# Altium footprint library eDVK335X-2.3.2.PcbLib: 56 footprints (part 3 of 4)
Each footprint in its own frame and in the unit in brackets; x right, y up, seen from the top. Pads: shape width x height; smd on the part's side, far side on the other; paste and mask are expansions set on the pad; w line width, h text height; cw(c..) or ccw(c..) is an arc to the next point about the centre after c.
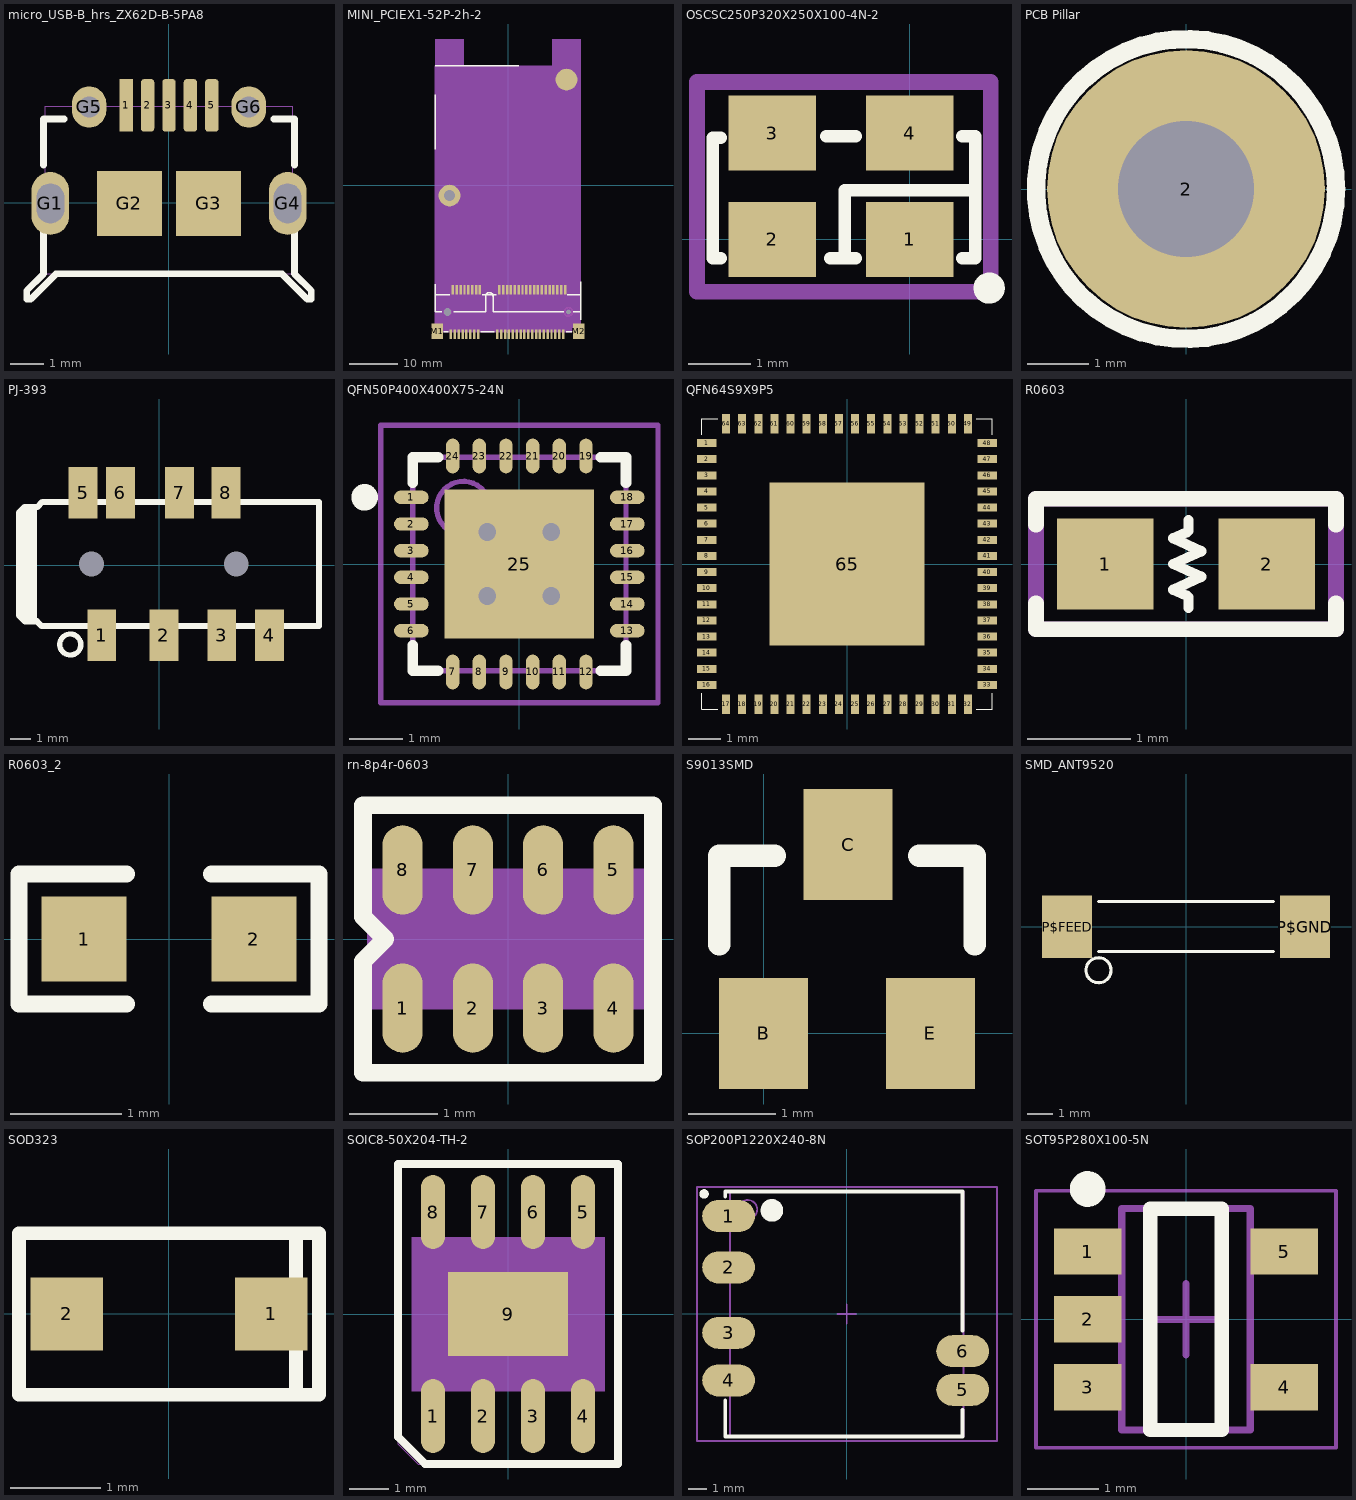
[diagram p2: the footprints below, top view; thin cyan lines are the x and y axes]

## micro_USB-B_hrs_ZX62D-B-5PA8 [mil] "MICRO_USB-B_HRS_ZX62D-B-5PA8"
pads (11):
  rect 16x63 smd: 1(-51.18,116.29)
  rrect50% 16x63 smd: 2(-25.59,116.29) 3(0,116.29) 4(25.59,116.29) 5(51.18,116.29)
  oval 45x75 / inner round 60 / far side oval 45x75 hole 33 slot 47.24 at 90 deg: G1(-141.73,-0.84) G4(141.74,-0.84)
  rect 78x78 smd: G2(-47.24,-0.84) G3(47.25,-0.84)
  oval 41.34x49.21 / inner round 60 / far side oval 41.34x49.21 hole 25.59: G5(-95.47,114.37) G6(95.47,114.37)
Top Overlay:
  lines w7.87: -150,-30.04 -150,-85.04 -170,-105.04 -170,-115.04 -165,-115.04 -135,-85.04 135,-85.04 165,-115.04 170,-115.04 170,-105.04 150,-85.04 150,-30.04 ; -150,45 -150,100 -125,100 ; 125,100 150,100 150,45
Mechanical 8:
  text "1" at -55.18,116.29 h10
  text "2" at -29.59,116.29 h10
  text "3" at -4,116.29 h10
  text "G1" at -149.73,-0.84 h10
  text "G5" at -103.47,114.37 h10
  text "G2" at -55.24,-0.84 h10
  text "4" at 21.59,116.29 h10
  text "5" at 47.18,116.29 h10
  text "G6" at 87.47,114.37 h10
  text "G3" at 39.25,-0.84 h10
Mechanical 10:
  lines w1: -135,-85.04 -165,-115.04 -170,-115.04 -170,-105.04 -168,-105.04 -148,-85.04 ; 135,-85.04 165,-115.04 170,-115.04 170,-105.04 168,-105.04 148,-85.04 ; -148,-85.04 -148,114.96 148,114.96 148,-85.04 ; -148,-85.04 148,-85.04

## MINI_PCIEX1-52P-2h-2 [mm] "MINI_PCIEX1-52P-2H-2"
pads (58):
  rect 0.508x2.007 smd: 1(-11.8,-30.775) 2(-11.4,-21.575) 3(-11,-30.775) 4(-10.6,-21.575) 5(-10.2,-30.775) 6(-9.8,-21.575) 7(-9.4,-30.775) 8(-9,-21.575) 9(-8.6,-30.775) 10(-8.2,-21.575) 11(-7.8,-30.775) 12(-7.4,-21.575) 13(-7,-30.775) 14(-6.6,-21.575) 15(-6.2,-30.775) 16(-5.8,-21.575) 17(-2.2,-30.775) 18(-1.8,-21.575) 19(-1.4,-30.775) 20(-1,-21.575) 21(-0.6,-30.775) 22(-0.2,-21.575) 23(0.2,-30.775) 24(0.6,-21.575) 25(1,-30.775) 26(1.4,-21.575) 27(1.8,-30.775) 28(2.2,-21.575) 29(2.6,-30.775) 30(3,-21.575) 31(3.4,-30.775) 32(3.8,-21.575) 33(4.2,-30.775) 34(4.6,-21.575) 35(5,-30.775) 36(5.4,-21.575) 37(5.8,-30.775) 38(6.2,-21.575) 39(6.6,-30.775) 40(7,-21.575) 41(7.4,-30.775) 42(7.8,-21.575) 43(8.2,-30.775) 44(8.6,-21.575) 45(9,-30.775) 46(9.4,-21.575) 47(9.8,-30.775) 48(10.2,-21.575) 49(10.6,-30.775) 50(11,-21.575) 51(11.4,-30.775) 52(11.8,-21.575)
  round 0 hole 1.6 unplated: G1(-12.5,-26.175)
  round 0 hole 1.092 unplated: G2(12.5,-26.175)
  rect 2.311x3.2 smd: M1(-14.65,-30.175) M2(14.65,-30.175)
  round 4.5 / inner round 1.524 / far side round 3 all layers, no hole: mPCIe_PIL(12.1,21.875)
  round 4.5 / inner round 1.524 / far side round 3 hole 2.3: ""(-12.095,-2.105)
Top Overlay:
  lines w0.3: -15,-22.675 -12,-22.675 ; -15,-20.425 -15,-26.175 -13.7,-26.175 ; -15,7.5 -15,18.725 ; -15,24.765 2.265,24.765 ; -13.3,-30.275 -12.4,-30.275 ; -11.2,-26.175 -4.6,-26.175 -4.6,-22.925 cw(c-3.85,-22.925) -3.1,-22.925 -3.1,-26.175 11.5,-26.175 ; -5.6,-30.275 -2.8,-30.275 ; -5.3,-22.675 -2.4,-22.675 ; 12,-30.275 13.3,-30.275 ; 12.3,-22.675 15,-22.675 ; 13.5,-26.175 15,-26.175 ; 15,-27.775 15,-19.975
Mechanical 8:
  text "52" at 11.597,-21.575 h0.25
  text "50" at 10.797,-21.575 h0.25
  text "48" at 9.997,-21.575 h0.25
  text "G2" at 12.297,-26.175 h0.25
  text "42" at 7.597,-21.575 h0.25
  text "40" at 6.797,-21.575 h0.25
  text "46" at 9.197,-21.575 h0.25
  text "44" at 8.397,-21.575 h0.25
  text "32" at 3.597,-21.575 h0.25
  text "34" at 4.397,-21.575 h0.25
  text "30" at 2.797,-21.575 h0.25
  text "38" at 5.997,-21.575 h0.25
  text "36" at 5.197,-21.575 h0.25
  text "24" at 0.397,-21.575 h0.25
  text "22" at -0.403,-21.575 h0.25
  text "28" at 1.997,-21.575 h0.25
  text "26" at 1.197,-21.575 h0.25
  text "M2" at 14.447,-30.175 h0.25
  text "51" at 11.197,-30.775 h0.25
  text "49" at 10.397,-30.775 h0.25
  text "47" at 9.597,-30.775 h0.25
  text "45" at 8.797,-30.775 h0.25
  text "43" at 7.997,-30.775 h0.25
  text "41" at 7.197,-30.775 h0.25
  text "33" at 3.997,-30.775 h0.25
  text "35" at 4.797,-30.775 h0.25
  text "31" at 3.197,-30.775 h0.25
  text "39" at 6.397,-30.775 h0.25
  text "37" at 5.597,-30.775 h0.25
  text "25" at 0.797,-30.775 h0.25
  text "23" at -0.003,-30.775 h0.25
  text "29" at 2.397,-30.775 h0.25
  text "27" at 1.597,-30.775 h0.25
  text "20" at -1.203,-21.575 h0.25
  text "18" at -2.003,-21.575 h0.25
  text "16" at -6.003,-21.575 h0.25
  text "8" at -9.102,-21.575 h0.25
  text "10" at -8.403,-21.575 h0.25
  text "6" at -9.902,-21.575 h0.25
  text "14" at -6.803,-21.575 h0.25
  text "12" at -7.603,-21.575 h0.25
  text "4" at -10.702,-21.575 h0.25
  text "2" at -11.502,-21.575 h0.25
  text "G1" at -12.703,-26.175 h0.25
  text "19" at -1.603,-30.775 h0.25
  text "21" at -0.803,-30.775 h0.25
  text "17" at -2.403,-30.775 h0.25
  text "11" at -8.003,-30.775 h0.25
  text "15" at -6.403,-30.775 h0.25
  text "13" at -7.203,-30.775 h0.25
  text "7" at -9.502,-30.775 h0.25
  text "9" at -8.702,-30.775 h0.25
  text "3" at -11.102,-30.775 h0.25
  text "5" at -10.302,-30.775 h0.25
  text "M1" at -14.853,-30.175 h0.25
  text "1" at -11.902,-30.775 h0.25
Mechanical 9:
  region: -2.4,-20.775 -2.4,-22.675 12.5,-22.675 12.5,-20.775
  region: 15,30.275 15,18.975 9.2,18.975 9.2,20.825 -9.2,20.825 -9.2,18.975 -15,18.975 -15,30.275 -9.2,30.275 -9.2,24.775 9.2,24.775 9.2,30.275
  region: -5.2,-20.775 -5.2,-22.675 -12,-22.675 -12,-20.775
  region: 15,-22.675 15,18.975 9.2,18.975 9.2,20.825 -9.2,20.825 -9.2,18.975 -15,18.975 -15,-22.675 -12,-22.675 -12,-20.775 -5.2,-20.775 -5.2,-22.675 -2.4,-22.675 -2.4,-20.775 12.5,-20.775 12.5,-22.675
  region: 15,-22.675 15,-30.275 -15,-30.275 -15,-22.675
Mechanical 10:
  lines w0.025: -15,-30.275 15,-30.275 15,-22.675 -15,-22.675 -15,-30.275 ; -15,-26.175 -4.6,-26.175 -4.6,-22.925 cw(c-3.85,-22.925) -3.1,-22.925 -3.1,-26.175 15,-26.175 15,24.775 -15,24.775 -15,-26.175
Multi-Layer keep-out:
  circle w0.025: c12.5,-26.175 r0.851

## OSCSC250P320X250X100-4N-2 [mm] "Crystal, SM; 4 Leads; Body 3.2 x 2.5 x 1.0 mm (LxWxH)"
height 1
pads (4):
  rect 1.4x1.2 smd: 1(0,0) 2(-2.2,0) 3(-2.2,1.7) 4(0,1.7)
Top Overlay:
  circle w0.25: c1.27,-0.78 r0.125
  lines w0.2: -3.023,-0.3 -3.15,-0.3 -3.15,1.626 -3.023,1.626 ; -1.34,1.651 -0.864,1.651 ; -1.27,-0.3 -0.864,-0.3 ; -1.041,-0.3 -1.041,0.787 1.041,0.787 ; 0.838,-0.3 1.05,-0.3 1.05,1.651 0.838,1.651
Mechanical 15:
  lines w0.254: -3.404,-0.838 -3.404,2.515 1.295,2.515 1.295,-0.838 -3.404,-0.838
3D body: height 1.1, standoff 0, extent -2.852,-0.652 0.752,2.302

## PCB Pillar [mm]
height 4.6
pads (1):
  round 4.5 / inner round 0 / far side round 3 hole 2.2: 2(0,0)
Top Overlay:
  circle w0.3: c0,0 r2.431

## PJ-393 [mm] "Audio Jack"
pads (10):
  rect 1.4x2.5 smd mask+0.08: 1(-2.79,-3.38) 2(0.21,-3.38) 3(3.01,-3.38) 4(5.31,-3.38) 5(-3.69,3.52) 6(-1.89,3.52) 7(0.96,3.52) 8(3.21,3.52)
  round 0 hole 1.2 unplated: 24(3.71,0.07) 25(-3.29,0.07)
Top Overlay:
  circle w0.254: c-4.311,-3.822 r0.51
  rectangle: -6.66,-2.702 -5.921,2.688
  lines w0.3: -6.79,-2.418 -6.79,2.558 -6.53,2.818 -5.911,2.818 -5.659,3.07 7.71,3.07 7.71,-2.93 -5.693,-2.93 -5.921,-2.702 -6.506,-2.702 -6.79,-2.418

## QFN50P400X400X75-24N [mm] "QFN, 24-Leads, Body 4.0x4.0mm (max), Pitch 0.50mm, IPC Medium Density"
height 0.75
pads (25):
  oval 0.65x0.25 smd: 1(-2.025,1.25) 2(-2.025,0.75) 3(-2.025,0.25) 4(-2.025,-0.25) 5(-2.025,-0.75) 6(-2.025,-1.25) 13(2.025,-1.25) 14(2.025,-0.75) 15(2.025,-0.25) 16(2.025,0.25) 17(2.025,0.75) 18(2.025,1.25)
  oval 0.25x0.65 smd: 7(-1.25,-2.025) 8(-0.75,-2.025) 9(-0.25,-2.025) 10(0.25,-2.025) 11(0.75,-2.025) 12(1.25,-2.025) 19(1.25,2.025) 20(0.75,2.025) 21(0.25,2.025) 22(-0.25,2.025) 23(-0.75,2.025) 24(-1.25,2.025)
  rect 2.8x2.8 smd: 25(0,0)
via 0.6,-0.6 diameter 0.66 hole 0.33
via -0.6,-0.6 diameter 0.66 hole 0.33
via 0.6,0.6 diameter 0.66 hole 0.33
via -0.6,0.6 diameter 0.66 hole 0.33
Top Overlay:
  circle w0.25: c-2.9,1.25 r0.125
  lines w0.2: -2,-1.525 -2,-2 -1.525,-2 ; -2,1.525 -2,2 -1.525,2 ; 1.525,-2 2,-2 2,-1.525 ; 1.525,2 2,2 2,1.525
Mechanical 13:
  circle w0.1: c-1.05,1.05 r0.5
  lines w0.1: -2,-2 2,-2 2,2 -2,2 -2,-2
Mechanical 15:
  lines w0.1: -0.5,0 0.5,0 ; 0,-0.5 0,0.5 ; -2.6,-2.6 2.6,-2.6 2.6,2.6 -2.6,2.6 -2.6,-2.6
3D body: height 0.75, standoff 0.02, extent -2,-2 2,2

## QFN64S9X9P5 [mm] "QFN64S9X9P5"
pads (65):
  rect 0.6x0.25 smd mask+0.051: 1(-4.35,3.75) 2(-4.35,3.25) 3(-4.35,2.75) 4(-4.35,2.25) 5(-4.35,1.75) 6(-4.35,1.25) 7(-4.35,0.75) 8(-4.35,0.25) 9(-4.35,-0.25) 10(-4.35,-0.75) 11(-4.35,-1.25) 12(-4.35,-1.75) 13(-4.35,-2.25) 14(-4.35,-2.75) 15(-4.35,-3.25) 16(-4.35,-3.75) 33(4.35,-3.75) 34(4.35,-3.25) 35(4.35,-2.75) 36(4.35,-2.25) 37(4.35,-1.75) 38(4.35,-1.25) 39(4.35,-0.75) 40(4.35,-0.25) 41(4.35,0.25) 42(4.35,0.75) 43(4.35,1.25) 44(4.35,1.75) 45(4.35,2.25) 46(4.35,2.75) 47(4.35,3.25) 48(4.35,3.75)
  rect 0.25x0.6 smd mask+0.051: 17(-3.75,-4.35) 18(-3.25,-4.35) 19(-2.75,-4.35) 20(-2.25,-4.35) 21(-1.75,-4.35) 22(-1.25,-4.35) 23(-0.75,-4.35) 24(-0.25,-4.35) 25(0.25,-4.35) 26(0.75,-4.35) 27(1.25,-4.35) 28(1.75,-4.35) 29(2.25,-4.35) 30(2.75,-4.35) 31(3.25,-4.35) 32(3.75,-4.35) 49(3.75,4.35) 50(3.25,4.35) 51(2.75,4.35) 52(2.25,4.35) 53(1.75,4.35) 54(1.25,4.35) 55(0.75,4.35) 56(0.25,4.35) 57(-0.25,4.35) 58(-0.75,4.35) 59(-1.25,4.35) 60(-1.75,4.35) 61(-2.25,4.35) 62(-2.75,4.35) 63(-3.25,4.35) 64(-3.75,4.35)
  rect 4.8x5.05 smd mask+0.051: 65(0,0)
Top Overlay:
  lines w0.025: -4.5,-4 -4.5,-4.5 -4,-4.5 ; -4.5,4 -4.5,4.5 -4,4.5 ; 4,-4.5 4.5,-4.5 4.5,-4 ; 4,4.5 4.5,4.5 4.5,4

## R0603 [mil] "R0603"
pads (2):
  rect 37x35 smd: 1(-31,0) 2(31,0)
Top Overlay:
  lines w3.94: 0.27,-12.2 -4.92,-9.84 5.91,-4.92 -4.92,0 5.91,4.92 -4.92,9.84 0.27,12.2 ; 0.98,-16.73 0.98,-12.79 ; 0.98,12.8 0.98,16.73
  lines w6: -57.5,-15 -57.5,-25 57.5,-25 57.5,-15 ; -57.5,15 -57.5,25 57.5,25 57.5,15
Mechanical 8:
  text "1" at -21,0 h25
Mechanical 10:
  lines w6: -57.5,-25 57.5,-25 57.5,25 -57.5,25 -57.5,-25

## R0603_2 [mil]
pads (2):
  rect 30x30 smd mask+2: 1(-30,0) 2(30,0)
Top Overlay:
  lines w6: -15,-23 -52.99,-23 -53,22.99 -15,23 ; 15,-23 52.99,-23 53,22.99 15,23

## rn-8p4r-0603 [mil] "RN-8P4R-0603"
pads (8):
  oval 18x40 smd: 1(-47.25,-31) 2(-15.75,-31) 3(15.75,-31) 4(47.25,-31) 5(47.25,31) 6(15.75,31) 7(-15.75,31) 8(-47.25,31)
Top Overlay:
  lines w7.87: -65,-60 65,-60 65,60 -65,60 -65,10 -55,0 -65,-10 -65,-60
Mechanical 8:
  text "5" at 45,16 h10
  text "4" at 45,-44 h10
  text "6" at 15,16 h10
  text "7" at -15,16 h10
  text "3" at 15,-44 h10
  text "2" at -15,-44 h10
  text "8" at -45,16 h10
  text "1" at -45,-44 h10
Mechanical 9:
  region: -63,31.5 63,31.5 63,-31.5 -63,-31.5
Mechanical 10:
  lines w1: -65,-60 65,-60 65,60 -65,60
  text ".Designator" at -17,-3.33 h10
  text "22R" at -50,-30 h31

## S9013SMD [mil]
pads (3):
  rect 40x50 smd: B(-0.02,-0.16) C(37.98,84.84) E(74.98,-0.16)
Top Overlay:
  lines w10: -20.02,39.84 -20.02,79.84 4.98,79.84 ; 69.98,79.84 94.98,79.84 94.98,39.84

## SMD_ANT9520 [mm]
pads (2):
  rect 2x2.5 smd: P$FEED(-4.75,0) P$GND(4.75,0)
Top Overlay:
  circle w0.127: c-3.5,-1.75 r0.5
  lines w0.127: -3.5,-1 3.5,-1 ; -3.5,1 3.5,1

## SOD323 [mil] "SOD323"
pads (2):
  rect 31.5x31.5 smd mask+2: 1(44.29,0) 2(-44.29,0)
Top Overlay:
  lines w6: 55,-35 55,35 ; -65,-35 65,-35 65,35 -65,35 -65,-35

## SOIC8-50X204-TH-2 [mil] "SOIC8-50X204-TH-2"
pads (9):
  oval 24x74 smd: 1(-75,-102) 2(-25,-102) 3(25,-102) 4(75,-102) 5(75,102) 6(25,102) 7(-25,102) 8(-75,102)
  rect 120x84 smd: 9(0,0)
Top Overlay:
  lines w8: -110,-122.83 -110,150 -100,150 110,150 110,-150 -82.83,-150 -110,-122.83
Mechanical 8:
  text "9" at 0,-4 h10
  text "7" at -25,98 h10
  text "4" at 75,-106 h10
  text "6" at 25,98 h10
  text "8" at -75,98 h10
  text "1" at -75,-106 h10
  text "5" at 75,98 h10
  text "3" at 25,-106 h10
  text "2" at -25,-106 h10
Mechanical 9:
  region: -96.5,-77 96.5,-77 96.5,77 -96.5,77
Mechanical 10:
  lines w1: -110,-130 -110,150 110,150 110,-150 -90,-150 -110,-130
  text "TPS54332D" at -70,-50 h20
  text ".Designator" at -70,30 h20

## SOP200P1220X240-8N [mm] "SOP, 8-Leads, Body 13.0x12.4mm (max), Pitch 2.00mm, IPC Medium Density"
height 2.4
pads (6):
  oval 2.8x1.7 smd: 1(-6.275,5.2) 2(-6.275,2.475) 3(-6.275,-1) 4(-6.275,-3.525) 5(6.15,-4.025) 6(6.15,-1.975)
Top Overlay:
  circle w0.25: c-7.575,6.375 r0.125
  circle w0.6: c-3.975,5.5 r0.3
  lines w0.2: -6.45,-4.575 -6.45,-6.5 6.15,-6.5 6.15,-5.1 ; -6.45,6.225 -6.45,6.5 6.15,6.5 6.15,-0.875
Mechanical 13:
  circle w0.1: c-5.25,5.55 r0.5
  lines w0.1: -6.2,-6.5 -6.2,6.5 6.2,6.5 6.2,-6.5 -6.2,-6.5
Mechanical 15:
  lines w0.1: -0.5,0 0.5,0 ; 0,-0.5 0,0.5 ; -7.95,6.75 -7.95,6.75 ; -7.95,6.75 -7.95,-6.75 7.975,-6.75 7.975,6.75 -7.95,6.75
3D body: height 2.4, standoff 0.25, extent -6.2,-6.5 6.2,6.5

## SOT95P280X100-5N [mm]
pads (5):
  rect 0.95x0.65 smd mask+0.051: 1(-1.375,0.95) 2(-1.375,0) 3(-1.375,-0.95) 4(1.375,-0.95) 5(1.375,0.95)
Top Overlay:
  circle w0.25: c-1.375,1.825 r0.125
  lines w0.2: -0.5,-1.55 -0.5,1.55 0.5,1.55 0.5,-1.55 -0.5,-1.55
Mechanical 13:
  lines w0.1: -0.9,-1.55 0.9,-1.55 0.9,1.55 -0.9,1.55 -0.9,-1.55
Mechanical 15:
  lines w0.05: -2.1,-1.8 2.1,-1.8 2.1,1.8 -2.1,1.8 -2.1,-1.8
  lines w0.1: -0.5,0 0.5,0 ; 0,-0.5 0,0.5
3D body: height 1, standoff 0.1, extent -0.9,-1.55 0.9,1.55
